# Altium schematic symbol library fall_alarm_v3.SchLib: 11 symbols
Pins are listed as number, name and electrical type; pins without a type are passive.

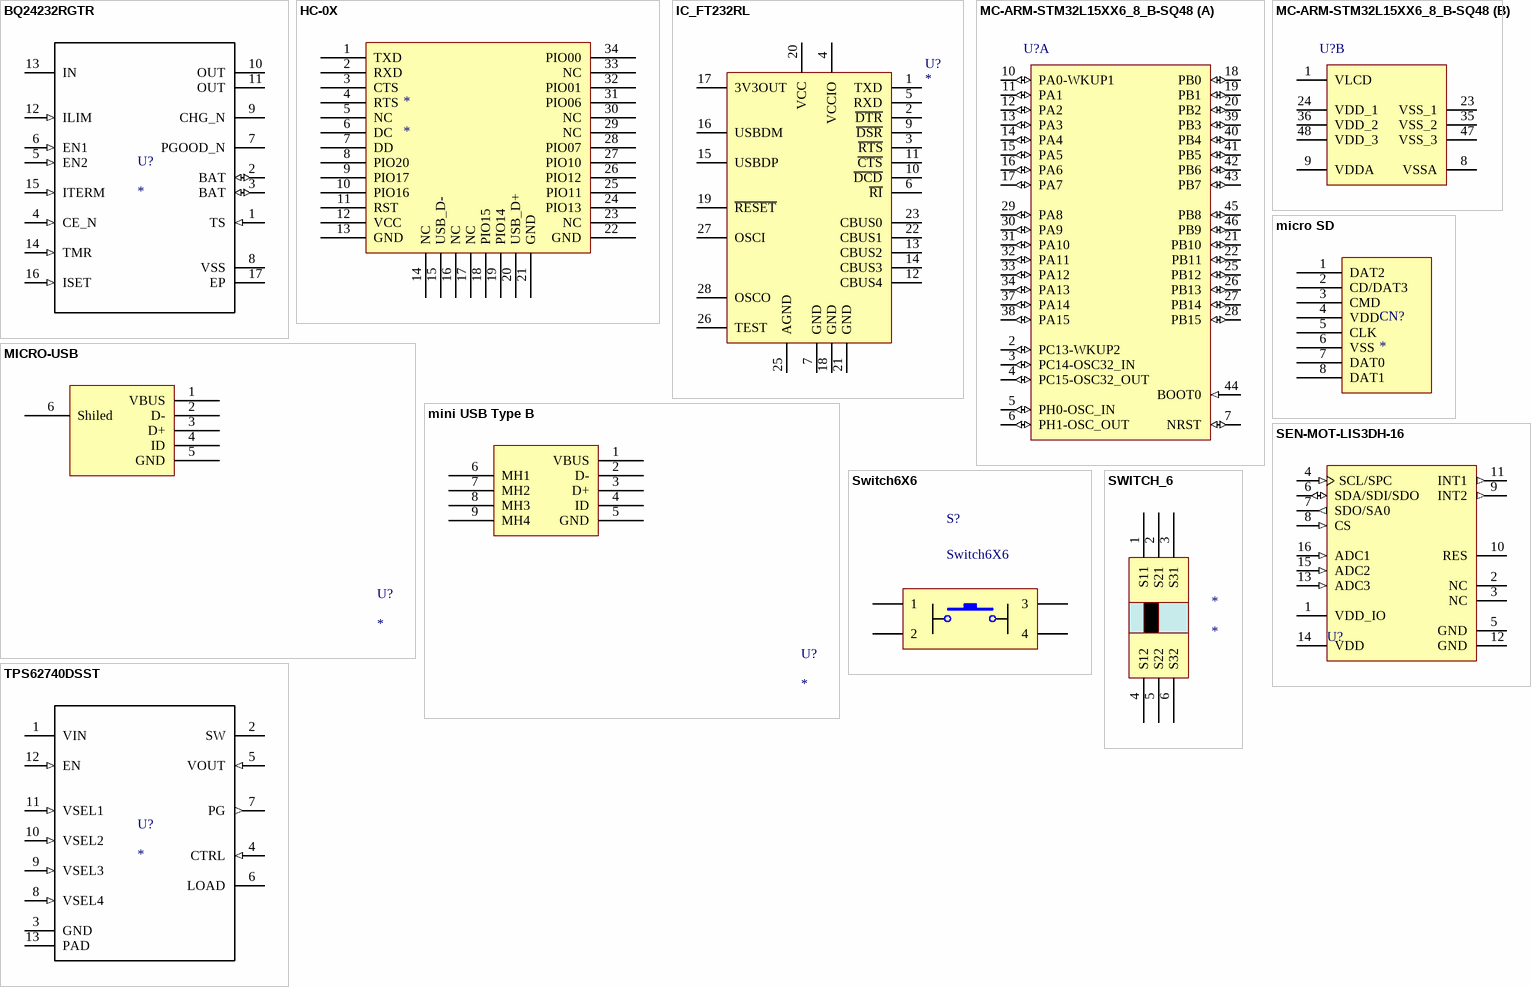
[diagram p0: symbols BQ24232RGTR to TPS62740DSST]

## BQ24232RGTR
designator U?
Imported; PartNumber: BQ24232RGTR; Alternate PartNumber: BQ24232RGTT; Manufacturer: Texas Instruments; CompType: IC; PIN_COUNT: 17
footprint RGT0016C
pins: 1 TS (in), 2 BAT (io), 3 BAT (io), 4 CE_N (in), 5 EN2 (in), 6 EN1 (in), 7 PGOOD_N (oc), 8 VSS (power), 9 CHG_N (oc), 10 OUT (power), 11 OUT (power), 12 ILIM (in), 13 IN (power), 14 TMR (in), 15 ITERM (in), 16 ISET (in), 17 EP (power)

## HC-0X
designator *
footprint HC-0X_4
pins: 1 TXD, 2 RXD, 3 CTS, 4 RTS, 5 NC, 6 DC, 7 DD, 8 PIO20, 9 PIO17, 10 PIO16, 11 RST, 12 VCC, 13 GND, 14 NC, 15 USB_D-, 16 NC, 17 NC, 18 PIO15, 19 PIO14, 20 USB_D+, 21 GND, 22 GND, 23 NC, 24 PIO13, 25 PIO11, 26 PIO12, 27 PIO10, 28 PIO07, 29 NC, 30 NC, 31 PIO06, 32 PIO01, 33 NC, 34 PIO00

## IC_FT232RL
designator U?
FT232R USB UART
footprint SSOP-28
pins: 1 TXD, 2 ~{DTR}, 3 ~{RTS}, 4 VCCIO, 5 RXD, 6 ~{RI}, 7 GND, 8 NC hidden to NC, 9 ~{DSR}, 10 ~{DCD}, 11 ~{CTS}, 12 CBUS4, 13 CBUS2, 14 CBUS3, 15 USBDP, 16 USBDM, 17 3V3OUT, 18 GND, 19 ~{RESET}, 20 VCC, 21 GND, 22 CBUS1, 23 CBUS0, 24 NC hidden to NC, 25 AGND, 26 TEST, 27 OSCI, 28 OSCO
2 alternate drawings of the same symbol

## MC-ARM-STM32L15XX6_8_B-SQ48
designator U?
footprint STM-LQFP48_N (QFP, 48-Leads, Body 7x7mm, Pitch 0.5mm, IPC Medium Density)
part A pins: 2 PC13-WKUP2 (io) "PC13-WKUP2/PC13/RTC_TAMP1/RTC_TS/RTC_OUT/WKUP2", 3 PC14-OSC32_IN (io) "PC14-OSC32_IN/PC14/OSC32_IN", 4 PC15-OSC32_OUT (io) "PC15-OSC32_OUT/PC15/OSC32_OUT", 5 PH0-OSC_IN (io) "PH0-OSC_IN/PH0/OSC_IN", 6 PH1-OSC_OUT (io) "PH1-OSC_OUT/PH1/OSC_OUT", 7 NRST (io), 10 PA0-WKUP1 (io) "PA0-WKUP1/PA0/WKUP1/USART2_CTS/ADC_IN0/TIM2_CH1_ETR/COMP1_INP", 11 PA1 (io) "PA1/USART2_RTS/ADC_IN1/TIM2_CH2/LCD_SEG0/COMP1_INP", 12 PA2 (io) "PA2/USART2_TX/ADC_IN2/TIM2_CH3/TIM9_CH1/LCD_SEG1/COMP1_INP", 13 PA3 (io) "PA3/USART2_RX/ADC_IN3/TIM2_CH4/TIM9_CH2/LCD_SEG2/COMP1_INP", 14 PA4 (io) "PA4/SPI1_NSS/USART2_CK/ADC_IN4/DAC_OUT1/COMP1_INP", 15 PA5 (io) "PA5/SPI1_SCK/ADC_IN5/DAC_OUT2/TIM2_CH1_ETR/COMP1_INP", 16 PA6 (io) "PA6/SPI1_MISO/ADC_IN6/TIM3_CH1/LCD_SEG3/TIM10_CH1/COMP1_INP", 17 PA7 (io) "PA7/SPI1_MOSI/ADC_IN7/TIM3_CH2/LCD_SEG4/TIM11_CH1/COMP1_INP", 18 PB0 (io) "PB0/ADC_IN8/TIM3_CH3/LCD_SEG5/COMP1_INP/VREF_OUT", 19 PB1 (io) "PB1/ADC_IN9/TIM3_CH4/LCD_SEG6/COMP1_INP/VREF_OUT", 20 PB2 (io) "PB2/BOOT1", 21 PB10 (io) "PB10/I2C2_SCL/USART3_TX/TIM2_CH3/LCD_SEG10", 22 PB11 (io) "PB11/I2C2_SDA/USART3_RX/TIM2_CH4/LCD_SEG11", 25 PB12 (io) "PB12/SPI2_NSS/I2C2_SMBA/USART3_CK/LCD_SEG12/ADC_IN18/COMP1_INP/TIM10_CH1", 26 PB13 (io) "PB13/SPI2_SCK/USART3_CTS/LCD_SEG13/ADC_IN19/COMP1_INP/TIM9_CH1", 27 PB14 (io) "PB14/SPI2_MISO/USART3_RTS/LCD_SEG14/ADC_IN20/COMP1_INP/TIM9_CH2", 28 PB15 (io) "PB15/SPI2_MOSI/LCD_SEG15/ADC_IN21/COMP1_INP/TIM11_CH1/RTC_REFIN", 29 PA8 (io) "PA8/USART1_CK/MCO/LCD_COM0", 30 PA9 (io) "PA9/USART1_TX/LCD_COM1", 31 PA10 (io) "PA10/USART1_RX/LCD_COM2", 32 PA11 (io) "PA11/USART1_CTS/USB_DM/SPI1_MISO", 33 PA12 (io) "PA12/USART1_RTS/USB_DP/SPI1_MOSI", 34 PA13 (io) "PA13/JTMS/SWDAT", 37 PA14 (io) "PA14/JTCK/SWCLK", 38 PA15 (io) "PA15/JTDI/TIM2_CH1_ETR/SPI1_NSS/LCD_SEG17", 39 PB3 (io) "PB3/JTDO/TIM2_CH2/SPI1_SCK/COMP2_INM/LCD_SEG7", 40 PB4 (io) "PB4/NJTRST/TIM3_CH1/SPI1_MISO/COMP2_INP/LCD_SEG8", 41 PB5 (io) "PB5/I2C1_SMBA/TIM3_CH2/SPI1_MOSI/COMP2_INP/LCD_SEG9", 42 PB6 (io) "PB6/I2C1_SCL/TIM4_CH1/USART1_TX", 43 PB7 (io) "PB7/I2C1_SDA/TIM4_CH2/USART1_RX/PVD_IN", 44 BOOT0 (in), 45 PB8 (io) "PB8/TIM4_CH3/I2C1_SCL/LCD_SEG16/TIM10_CH1", 46 PB9 (io) "PB9/TIM4_CH4/I2C1_SDA/LCD_COM3/TIM11_CH1"
part B pins: 1 VLCD (power), 8 VSSA (power), 9 VDDA (power), 23 VSS_1 (power), 24 VDD_1 (power), 35 VSS_2 (power), 36 VDD_2 (power), 47 VSS_3 (power), 48 VDD_3 (power)

## micro SD
designator CN?
footprint micro SD
pins: 1 DAT2, 2 CD/DAT3, 3 CMD, 4 VDD, 5 CLK, 6 VSS, 7 DAT0, 8 DAT1

## MICRO-USB
designator U?
footprint MICRO-USB
pins: 1 VBUS, 2 D-, 3 D+, 4 ID, 5 GND, 6 Shiled

## mini USB Type B
designator U?
footprint mini USB Type B
pins: 1 VBUS, 2 D-, 3 D+, 4 ID, 5 GND, 6 MH1, 7 MH2, 8 MH3, 9 MH4

## SEN-MOT-LIS3DH-16
designator U?
footprint LGA16-3X3X1_M (PQFN, 16-Leads, Body 3x3mm, Pitch 0.5mm, IPC Low Density)
pins: 1 VDD_IO (power), 2 NC, 3 NC, 4 SCL/SPC (in), 5 GND (power), 6 SDA/SDI/SDO (io), 7 SDO/SA0 (out), 8 CS (in), 9 INT2 (out), 10 RES, 11 INT1 (out), 12 GND (power), 13 ADC3 (in), 14 VDD (power), 15 ADC2 (in), 16 ADC1 (in)

## Switch6X6
designator S?
Switch
footprint Switch6X6
pins: 1, 2, 3, 4

## SWITCH_6
designator *
footprint SWITCH_6
pins: 1 S11, 2 S21, 3 S31, 4 S12, 5 S22, 6 S32

## TPS62740DSST
designator U?
Imported; PartNumber: TPS62740DSS; Alternate Manufacturer: None; Manufacturer: Texas Instruments; CurrentTime: Not shown in title block; DocumentNumber: 1; SymbolCreator: a0411947; CompType: IC; U/M: EA; Designator: U?; PIN_COUNT: 13
footprint DSS0012A
pins: 1 VIN (power), 2 SW (power), 3 GND (power), 4 CTRL (in), 5 VOUT (in), 6 LOAD (power), 7 PG (out), 8 VSEL4 (in), 9 VSEL3 (in), 10 VSEL2 (in), 11 VSEL1 (in), 12 EN (in), 13 PAD (power)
